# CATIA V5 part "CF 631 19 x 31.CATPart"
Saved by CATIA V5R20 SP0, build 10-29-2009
Part number: CF 631 19 x 31
Definition: NONE
Nomenclature: CF 631 19 x 31
Source: Unknown
Description: CF 631 19 x 31
Bounding box of the stored display mesh (mm): x -13 to 18, y -17 to 17, z -17 to 17
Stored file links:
  C:\Users\Utente\Desktop\IO LAVORO\3D X SITO CF\X SITO\CF 631\CF 631 19 x 31.CATPart
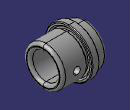
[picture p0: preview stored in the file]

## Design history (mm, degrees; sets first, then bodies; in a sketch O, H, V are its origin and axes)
Body1 "CF 631 19 x 31" (main body)
  Solid1: solid without history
